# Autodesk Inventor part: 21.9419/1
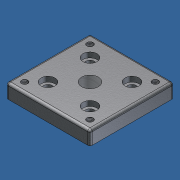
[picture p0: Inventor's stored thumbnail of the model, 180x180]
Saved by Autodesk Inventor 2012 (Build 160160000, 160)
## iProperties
Created: 2007-01
Part Number: 21.9419/1
Document SubType Name: Modeling
Designer: Andy Moles
Material: Aluminum-6061
Mass: 294.693 g
Surface Area: 240.573 cm^2
Volume: 108.743 cm^3
Density: 2.71 g/cm^3
Description: MACHINE TO 21.9419/1
Vendor: S
Stock Number: 21.1059 B&T PLATE 90X90 GD
Author: Andy Moles
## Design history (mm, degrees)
sketch "Sketch1"
  geometry: L1 (-45, -45)-(45, -45); L2 (45, -45)-(45, 45); L3 (45, 45)-(-45, 45); L4 (-45, 45)-(-45, -45); L5 (-45, -45)-(45, 45); C1 r 4.5 at (-22.5, 22.5); C2 r 4.5 at (22.5, 22.5); C3 r 4.5 at (-22.5, -22.5); C4 r 4.5 at (22.5, -22.5); 2 further points
  constraints: 10 end point, 4 centre point, 2 parallel, 2 vertical alignment, 1 coincident, 1 horizontal, 1 midpoint, 1 perpendicular
  dimensions: "d0" = 90 distance of L2.end L3.end; "d1" = 90 distance of L3.end L1.start; "d2" = 9 diameter of C1; "d3" = 9 diameter of C2; "d4" = 22.5 distance from line of C1.centre L3; "d5" = 22.5 distance from line of L3 C2.centre; "d6" = 22.5 distance from line of C2.centre L2; "d7" = 22.5 distance from line of C1.centre L4; "d29" = 9 diameter of C3 (= d2); "d30" = 9 diameter of C4 (= d3); "d31" = 22.5 distance from line of C3.centre L1; "d32" = 22.5 distance from line of C4.centre L1
extrude "Extrusion1" new body sketch "Sketch1" distance "d8" = 15; taper "d9" = 0 deg
hole "Hole1" diameter "d12" = 15; stored, may be unused: countersink angle "d16" = 90 deg, drill point angle "d18" = 0 deg; dims "d10" = 10, "d11" = 10, "d13" = 6, "d14" = 4, "d15" = 2, "d17" = 5.5
hole "Hole2" diameter "d21" = 15; stored, may be unused: countersink angle "d25" = 90 deg, drill point angle "d27" = 0 deg; dims "d19" = 10, "d20" = 10, "d22" = 6, "d23" = 4, "d24" = 2, "d26" = 5.5
fillet "Fillet1" dims "d28" = 2.5
hole "Hole3" diameter "d35" = 15; stored, may be unused: countersink angle "d39" = 90 deg, drill point angle "d41" = 0 deg; dims "d33" = 10, "d34" = 10, "d36" = 6, "d37" = 4, "d38" = 2, "d40" = 5.5
hole "Hole4" diameter "d44" = 15; stored, may be unused: countersink angle "d48" = 90 deg, drill point angle "d50" = 0 deg; dims "d42" = 10, "d43" = 10, "d45" = 6, "d46" = 4, "d47" = 2, "d49" = 5.5
sketch "Sketch2"
  geometry: L1 (45, -42.5)-(45, 42.5) reference; L2 (-42.5, -45)-(42.5, -45) reference; L3 (-45, 42.5)-(-45, -42.5) reference; L4 (42.5, 45)-(-42.5, 45) reference; C1 r 4.5 at (-22.5, 22.5) reference; C2 r 4.5 at (22.5, 22.5) reference; C3 r 4.5 at (-22.5, -22.5) reference; C4 r 4.5 at (22.5, -22.5) reference; A1 r 2.5 centre (42.5, 42.5) between (45, 42.5) and (42.5, 45) reference; A2 r 2.5 centre (42.5, -42.5) between (42.5, -45) and (45, -42.5) reference; A3 r 2.5 centre (-42.5, -42.5) between (-45, -42.5) and (-42.5, -45) reference; A4 r 2.5 centre (-42.5, 42.5) between (-42.5, 45) and (-45, 42.5) reference; 5 further points
  dimensions: "d51" = 10 distance from line of point (-35, 35) L3; "d52" = 10 distance from line of point (-35, 35) L4; "d53" = 10 distance from line of point (35, 35) L4; "d54" = 10 distance from line of point (35, 35) L1; "d55" = 10 distance from line of point (35, -35) L1; "d56" = 10 distance from line of point (35, -35) L2; "d57" = 10 distance from line of point (-35, -35) L2; "d58" = 10 distance from line of point (-35, -35) L3
hole "Hole5" sketch "Sketch2" at (-35, -35), (-35, 35), (35, 35), (35, -35) diameter "d59" = 6.647; stored, may be unused: countersink angle "d63" = 90 deg, drill point angle "d65" = 118 deg; dims "d60" = 15, "d61" = 4, "d62" = 2, "d64" = 8
sketch "Sketch3"
  geometry: C1 r 9 at (0, 0); 1 further point
  constraints: 1 centre point, 1 coincident
  dimensions: "d66" = 18 diameter of C1
extrude "Extrusion2" cut sketch "Sketch3" stored distance "d67" = 10; taper "d68" = 0 deg
body "Solid1"
node "Projected Loop1"
